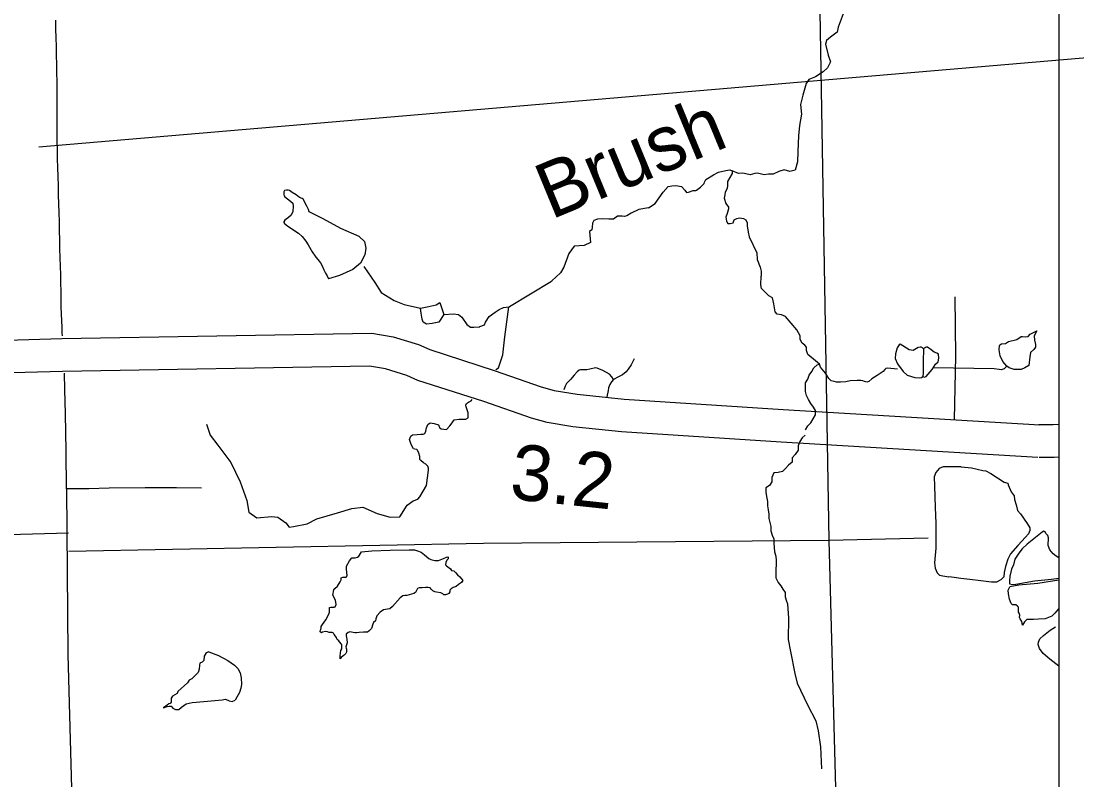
# Model space of a CAD drawing. Extents: x 1367863 to 1368197, y 380048 to 380261.
# Drawn here: x 1368072.73 to 1368103.87, y 380118.75 to 380141.12 of the extents above; entities that cross this region are included whole.
import ezdxf

# ---------------------------------------------------------------- set-up
doc = ezdxf.new("R2010")
doc.units = 0
for name, color, linetype in [('Level 10', 7, 'Continuous'), ('Level 31', 7, 'Continuous'), ('Level 32', 7, 'Continuous'), ('Level 35', 7, 'Continuous'), ('Level 48', 7, 'Continuous'), ('Level 5', 7, 'Continuous'), ('R_Draft', 7, 'Continuous'), ('R_No Plot', 7, 'Continuous')]:
    doc.layers.add(name, color=color, linetype=linetype)

msp = doc.modelspace()

# ---------------------------------------------------------------- linework, layer by layer
at = {"layer": 'Level 10'}
for points in [[(1368071.322, 380131.689), (1368073.931, 380131.759), (1368083.074, 380131.916), (1368083.701, 380131.811), (1368084.454, 380131.587), (1368084.786, 380131.435), (1368086.684, 380130.822), (1368088.074, 380130.341), (1368088.457, 380130.233), (1368089.133, 380130.121), (1368090.52, 380129.974), (1368095.213, 380129.671), (1368102.782, 380129.222)], [(1368102.724, 380128.253), (1368095.153, 380128.702), (1368090.438, 380129.008), (1368089.002, 380129.159), (1368088.244, 380129.285), (1368087.783, 380129.415), (1368086.377, 380129.902), (1368084.433, 380130.529), (1368084.112, 380130.677), (1368083.482, 380130.864), (1368083.002, 380130.944), (1368073.953, 380130.789), (1368071.363, 380130.72)], [(1368102.747, 380129.223), (1368103.169, 380129.227), (1368103.344, 380129.239)], [(1368103.344, 380128.267), (1368103.206, 380128.258), (1368102.759, 380128.252)]]:
    msp.add_lwpolyline(points, dxfattribs=at)
at = {"layer": 'Level 31'}
for points in [[(1368073.947, 380131.842), (1368073.945, 380131.925), (1368073.941, 380132.1), (1368073.93, 380132.288), (1368073.923, 380132.489), (1368073.914, 380132.699), (1368073.915, 380132.927), (1368073.91, 380133.158), (1368073.904, 380133.397), (1368073.898, 380133.644), (1368073.891, 380133.895), (1368073.885, 380134.151), (1368073.876, 380134.411), (1368073.87, 380134.674), (1368073.864, 380134.938), (1368073.865, 380135.211), (1368073.851, 380135.473), (1368073.842, 380135.738), (1368073.835, 380136.004), (1368073.828, 380136.27), (1368073.82, 380136.537), (1368073.814, 380136.802), (1368073.808, 380137.065), (1368073.8, 380137.326), (1368073.797, 380137.585), (1368073.795, 380137.837), (1368073.797, 380138.091), (1368073.797, 380138.34), (1368073.793, 380138.591), (1368073.796, 380138.84), (1368073.794, 380139.093), (1368073.79, 380139.345), (1368073.787, 380139.598), (1368073.782, 380139.853), (1368073.776, 380140.111), (1368073.77, 380140.372), (1368073.764, 380140.633), (1368073.758, 380140.894), (1368073.753, 380141.154)], [(1368074.069, 380127.329), (1368074.054, 380128.437), (1368074.041, 380129.554), (1368074.02, 380130.246), (1368074.008, 380130.745)], [(1368078.05, 380127.349), (1368077.312, 380127.356), (1368076.391, 380127.356), (1368075.327, 380127.349), (1368074.731, 380127.329), (1368074.318, 380127.329), (1368074.069, 380127.329)], [(1368074.069, 380127.329), (1368074.105, 380122.448), (1368074.225, 380118.134)], [(1368103.344, 380122.103), (1368103.078, 380122.303), (1368102.88, 380122.476), (1368102.774, 380122.622), (1368102.734, 380122.741), (1368102.738, 380122.812), (1368102.782, 380122.904), (1368102.888, 380123.002), (1368103.083, 380123.161), (1368103.246, 380123.258)]]:
    msp.add_lwpolyline(points, dxfattribs=at)
at = {"layer": 'Level 32'}
for points in [[(1368100.259, 380129.371), (1368100.304, 380131.239), (1368100.281, 380132.997)], [(1368090.815, 380131.165), (1368090.728, 380130.982), (1368090.64, 380130.863), (1368090.577, 380130.784), (1368090.465, 380130.696), (1368090.354, 380130.632), (1368090.203, 380130.553), (1368090.147, 380130.489), (1368090.1, 380130.41), (1368090.06, 380130.306), (1368090.044, 380130.227), (1368090.01, 380130.046)], [(1368090.203, 380130.553), (1368090.155, 380130.632), (1368090.084, 380130.712), (1368089.893, 380130.823), (1368089.726, 380130.887), (1368089.67, 380130.895), (1368089.503, 380130.855), (1368089.416, 380130.839), (1368089.32, 380130.839), (1368089.233, 380130.839), (1368089.193, 380130.831), (1368089.129, 380130.784), (1368089.042, 380130.68), (1368088.939, 380130.553), (1368088.819, 380130.434), (1368088.78, 380130.362), (1368088.735, 380130.254)]]:
    msp.add_lwpolyline(points, dxfattribs=at)
at = {"layer": 'Level 35'}
for points in [[(1368097.066, 380141.572), (1368096.831, 380140.945), (1368096.802, 380140.799), (1368096.606, 380140.652), (1368096.489, 380140.554), (1368096.459, 380140.446), (1368096.538, 380140.123), (1368096.606, 380139.918), (1368096.518, 380139.741), (1368096.391, 380139.624), (1368096.166, 380139.477), (1368095.97, 380139.399), (1368095.882, 380139.281), (1368095.784, 380138.939), (1368095.715, 380138.665), (1368095.745, 380138.381), (1368095.686, 380138.048), (1368095.657, 380137.744), (1368095.637, 380137.275), (1368095.627, 380136.971), (1368095.567, 380136.728), (1368095.404, 380136.69), (1368095.24, 380136.74), (1368095.077, 380136.69), (1368094.914, 380136.614), (1368094.775, 380136.614), (1368094.65, 380136.589), (1368094.448, 380136.64), (1368094.373, 380136.627), (1368094.235, 380136.589), (1368094.021, 380136.64), (1368093.895, 380136.627), (1368093.7, 380136.712)], [(1368091.239, 380135.617), (1368091.433, 380135.749), (1368091.666, 380136.083), (1368091.821, 380136.246), (1368091.922, 380136.269), (1368092.038, 380136.277), (1368092.209, 380136.246), (1368092.31, 380136.137), (1368092.357, 380136.067), (1368092.419, 380136.083), (1368092.551, 380136.129), (1368092.636, 380136.129), (1368092.652, 380136.137), (1368092.768, 380136.23), (1368092.877, 380136.331), (1368092.892, 380136.37), (1368092.931, 380136.455), (1368093.149, 380136.587), (1368093.296, 380136.673), (1368093.513, 380136.719), (1368093.638, 380136.735), (1368093.7, 380136.712), (1368093.7, 380136.626), (1368093.568, 380136.393), (1368093.568, 380136.277), (1368093.56, 380136.191), (1368093.498, 380136.083), (1368093.49, 380135.997), (1368093.467, 380135.904), (1368093.521, 380135.749), (1368093.591, 380135.64), (1368093.591, 380135.586), (1368093.552, 380135.446), (1368093.521, 380135.337), (1368093.537, 380135.228), (1368093.575, 380135.159), (1368093.645, 380135.151), (1368093.731, 380135.174), (1368093.762, 380135.259), (1368093.839, 380135.306), (1368093.925, 380135.322), (1368094.041, 380135.298), (1368094.111, 380135.259), (1368094.142, 380135.174), (1368094.15, 380135.089), (1368094.173, 380134.902), (1368094.204, 380134.762), (1368094.429, 380134.293), (1368094.445, 380134.092), (1368094.53, 380133.866), (1368094.561, 380133.75), (1368094.561, 380133.602)], [(1368082.856, 380134.627), (1368082.7, 380134.774), (1368082.164, 380135.012), (1368081.637, 380135.294), (1368081.264, 380135.478), (1368081.223, 380135.503), (1368081.207, 380135.572), (1368081.158, 380135.667), (1368081.052, 380135.871), (1368081.023, 380135.896), (1368080.945, 380135.924), (1368080.847, 380135.998), (1368080.724, 380136.068), (1368080.647, 380136.129), (1368080.61, 380136.137), (1368080.561, 380136.133), (1368080.503, 380136.125), (1368080.483, 380136.092), (1368080.483, 380136.027), (1368080.483, 380136.014), (1368080.491, 380135.973), (1368080.508, 380135.937), (1368080.63, 380135.851), (1368080.745, 380135.752), (1368080.753, 380135.662), (1368080.745, 380135.507), (1368080.7, 380135.405), (1368080.618, 380135.327), (1368080.553, 380135.282), (1368080.512, 380135.249), (1368080.479, 380135.204), (1368080.475, 380135.184), (1368080.503, 380135.155), (1368080.602, 380135.081), (1368080.908, 380134.873), (1368081.023, 380134.774), (1368081.133, 380134.631), (1368081.195, 380134.521), (1368081.313, 380134.32), (1368081.424, 380134.164), (1368081.485, 380134.091), (1368081.563, 380133.997), (1368081.608, 380133.907), (1368081.657, 380133.784), (1368081.706, 380133.686), (1368081.755, 380133.612), (1368081.8, 380133.526)], [(1368091.239, 380135.617), (1368090.952, 380135.57), (1368090.727, 380135.461), (1368090.595, 380135.384), (1368090.532, 380135.36), (1368090.455, 380135.368), (1368090.323, 380135.368), (1368090.206, 380135.283), (1368090.067, 380135.283), (1368089.88, 380135.29), (1368089.733, 380135.283), (1368089.624, 380135.244), (1368089.585, 380135.166), (1368089.578, 380135.05), (1368089.562, 380134.972), (1368089.5, 380134.918), (1368089.529, 380134.593), (1368089.337, 380134.508), (1368089.04, 380134.487), (1368088.891, 380134.274), (1368088.742, 380133.87), (1368088.636, 380133.7), (1368088.381, 380133.466), (1368088.373, 380133.447), (1368087.14, 380132.699)], [(1368082.856, 380134.627), (1368082.897, 380134.426), (1368082.864, 380134.234), (1368082.737, 380133.984), (1368082.512, 380133.796), (1368082.119, 380133.62), (1368081.8, 380133.526)], [(1368082.843, 380133.882), (1368083.162, 380133.414), (1368083.353, 380133.116), (1368083.736, 380132.882), (1368084.026, 380132.769), (1368084.506, 380132.656)], [(1368098.577, 380130.863), (1368098.29, 380130.889), (1368098.239, 380130.882), (1368098.204, 380130.849), (1368098.161, 380130.788), (1368097.983, 380130.674), (1368097.821, 380130.575), (1368097.74, 380130.494), (1368097.679, 380130.474), (1368097.603, 380130.496), (1368097.555, 380130.517), (1368097.497, 380130.529), (1368097.395, 380130.527), (1368097.187, 380130.517), (1368097.058, 380130.489), (1368096.898, 380130.479), (1368096.782, 380130.479), (1368096.716, 380130.494), (1368096.629, 380130.517), (1368096.551, 380130.588), (1368096.457, 380130.742), (1368096.305, 380130.917), (1368096.28, 380131.011), (1368096.163, 380131.102), (1368095.933, 380131.288), (1368095.901, 380131.407), (1368095.901, 380131.511), (1368095.846, 380131.566), (1368095.766, 380131.622), (1368095.711, 380131.733), (1368095.711, 380131.844), (1368095.608, 380132.019), (1368095.274, 380132.416), (1368095.155, 380132.464), (1368095.036, 380132.479), (1368094.972, 380132.551), (1368094.932, 380132.789), (1368094.893, 380132.964), (1368094.782, 380133.019), (1368094.567, 380133.242), (1368094.551, 380133.345), (1368094.561, 380133.602)], [(1368084.506, 380132.656), (1368084.703, 380132.698), (1368084.971, 380132.755), (1368085.084, 380132.825), (1368085.197, 380132.472), (1368085.056, 380132.247), (1368084.859, 380132.204), (1368084.689, 380132.19), (1368084.591, 380132.247), (1368084.562, 380132.331), (1368084.534, 380132.515), (1368084.506, 380132.656)], [(1368085.197, 380132.472), (1368085.487, 380132.489), (1368085.634, 380132.474), (1368085.727, 380132.388), (1368085.875, 380132.179), (1368085.983, 380132.101), (1368086.084, 380132.101), (1368086.263, 380132.109), (1368086.263, 380132.117), (1368086.403, 380132.171), (1368086.426, 380132.241), (1368086.535, 380132.412), (1368086.713, 380132.544), (1368086.83, 380132.614), (1368086.962, 380132.676), (1368087.117, 380132.699), (1368087.14, 380132.699)], [(1368086.736, 380130.847), (1368086.807, 380130.894), (1368086.935, 380131.277), (1368086.998, 380131.808), (1368087.117, 380132.699)], [(1368101.598, 380131.578), (1368101.649, 380131.604), (1368101.768, 380131.617), (1368101.854, 380131.671), (1368102.104, 380131.735), (1368102.229, 380131.822), (1368102.271, 380131.825), (1368102.357, 380131.815), (1368102.431, 380131.825), (1368102.492, 380131.889), (1368102.549, 380131.918), (1368102.693, 380131.985)], [(1368102.693, 380131.985), (1368102.613, 380131.844), (1368102.62, 380131.719), (1368102.652, 380131.588), (1368102.652, 380131.511), (1368102.604, 380131.437), (1368102.508, 380131.354), (1368102.482, 380131.219), (1368102.453, 380130.97)], [(1368099.195, 380131.497), (1368099.043, 380131.405), (1368098.924, 380131.426), (1368098.66, 380131.596), (1368098.627, 380131.58), (1368098.574, 380131.484), (1368098.521, 380131.312), (1368098.508, 380131.172), (1368098.576, 380131.017), (1368098.746, 380130.792), (1368098.863, 380130.68), (1368099.091, 380130.614), (1368099.22, 380130.601), (1368099.291, 380130.617), (1368099.327, 380130.639), (1368099.378, 380130.622), (1368099.431, 380130.645), (1368099.606, 380130.847), (1368099.702, 380131.005), (1368099.781, 380131.073), (1368099.796, 380131.185), (1368099.786, 380131.304), (1368099.74, 380131.327), (1368099.667, 380131.357), (1368099.573, 380131.426), (1368099.469, 380131.504), (1368099.433, 380131.507), (1368099.403, 380131.494), (1368099.35, 380131.456), (1368099.314, 380131.492), (1368099.279, 380131.512), (1368099.253, 380131.512), (1368099.203, 380131.499)], [(1368099.35, 380131.456), (1368099.335, 380131.088), (1368099.34, 380130.749), (1368099.327, 380130.639)], [(1368102.453, 380130.97), (1368102.338, 380130.899), (1368102.226, 380130.854), (1368102.027, 380130.845), (1368101.87, 380130.902), (1368101.803, 380130.947), (1368101.688, 380131.082), (1368101.611, 380131.251), (1368101.579, 380131.428), (1368101.585, 380131.556), (1368101.598, 380131.578)], [(1368095.868, 380129.065), (1368095.937, 380129.184), (1368096.022, 380129.278), (1368096.09, 380129.397), (1368096.158, 380129.508), (1368096.158, 380129.636), (1368096.099, 380129.738), (1368096.022, 380129.849), (1368095.954, 380129.96), (1368095.894, 380130.079), (1368095.868, 380130.199), (1368095.868, 380130.327), (1368095.868, 380130.455), (1368095.937, 380130.565), (1368095.979, 380130.685), (1368096.056, 380130.787), (1368096.116, 380130.898), (1368096.21, 380130.983), (1368096.28, 380131.011)], [(1368101.803, 380130.947), (1368101.723, 380130.867), (1368101.64, 380130.841), (1368101.582, 380130.854), (1368101.435, 380130.873), (1368099.636, 380130.896)], [(1368078.195, 380129.235), (1368078.302, 380128.917), (1368078.535, 380128.619), (1368078.918, 380128.109), (1368079.195, 380127.535), (1368079.386, 380126.982), (1368079.45, 380126.642), (1368079.684, 380126.472), (1368080.13, 380126.514), (1368080.3, 380126.493), (1368080.534, 380126.323), (1368080.641, 380126.195), (1368080.768, 380126.216), (1368081.172, 380126.301), (1368081.449, 380126.45), (1368082.065, 380126.62), (1368082.49, 380126.748), (1368082.809, 380126.79), (1368083.235, 380126.599), (1368083.617, 380126.493), (1368083.903, 380126.503), (1368084.121, 380126.844), (1368084.291, 380126.976), (1368084.431, 380127.023), (1368084.493, 380127.093), (1368084.687, 380127.427), (1368084.742, 380127.877), (1368084.742, 380127.939), (1368084.726, 380128.002), (1368084.672, 380128.056), (1368084.602, 380128.095), (1368084.524, 380128.165), (1368084.493, 380128.196), (1368084.493, 380128.281), (1368084.462, 380128.382), (1368084.423, 380128.467), (1368084.4, 380128.491), (1368084.346, 380128.499), (1368084.307, 380128.514), (1368084.237, 380128.638), (1368084.183, 380128.786), (1368084.221, 380128.887), (1368084.276, 380128.926), (1368084.416, 380128.933), (1368084.516, 380128.941), (1368084.594, 380128.941), (1368084.641, 380128.957), (1368084.672, 380129.027), (1368084.687, 380129.128), (1368084.726, 380129.229), (1368084.796, 380129.275), (1368084.912, 380129.26), (1368085.037, 380129.213), (1368085.075, 380129.135), (1368085.122, 380129.104), (1368085.277, 380129.081), (1368085.378, 380129.19), (1368085.44, 380129.275), (1368085.502, 380129.361), (1368085.65, 380129.384), (1368085.751, 380129.384), (1368085.852, 380129.384), (1368085.914, 380129.423), (1368085.921, 380129.477), (1368085.921, 380129.57), (1368085.859, 380129.749), (1368085.852, 380129.795), (1368085.867, 380129.85), (1368085.929, 380129.881), (1368086.007, 380129.927), (1368086.038, 380129.962)], [(1368095.86, 380128.911), (1368095.766, 380128.834), (1368095.698, 380128.724), (1368095.655, 380128.596), (1368095.647, 380128.468), (1368095.561, 380128.34), (1368095.476, 380128.246), (1368095.476, 380128.118), (1368095.365, 380128.024), (1368095.28, 380127.931), (1368095.186, 380127.845), (1368095.058, 380127.811), (1368094.93, 380127.803), (1368094.871, 380127.666), (1368094.871, 380127.538), (1368094.802, 380127.427), (1368094.7, 380127.359), (1368094.7, 380127.231), (1368094.717, 380127.103), (1368094.743, 380126.958), (1368094.743, 380126.831), (1368094.768, 380126.711), (1368094.785, 380126.583), (1368094.785, 380126.455)], [(1368100.463, 380127.98), (1368099.931, 380127.98), (1368099.808, 380127.926), (1368099.715, 380127.813), (1368099.66, 380127.68), (1368099.67, 380127.409), (1368099.69, 380126.793), (1368099.715, 380126.305), (1368099.715, 380125.576), (1368099.675, 380125.143), (1368099.695, 380124.99), (1368099.749, 380124.848), (1368099.818, 380124.788), (1368099.916, 380124.764), (1368100.099, 380124.734)], [(1368100.463, 380127.98), (1368100.767, 380127.951), (1368101.097, 380127.872), (1368101.191, 380127.862), (1368101.333, 380127.783), (1368101.727, 380127.527), (1368101.831, 380127.497), (1368101.845, 380127.448), (1368101.929, 380127.241), (1368102.023, 380127.128), (1368102.033, 380127.02), (1368102.077, 380126.862), (1368102.116, 380126.695), (1368102.205, 380126.591), (1368102.407, 380126.305), (1368102.486, 380126.182), (1368102.486, 380126.099), (1368102.441, 380126.005), (1368102.353, 380125.907), (1368102.126, 380125.66), (1368101.919, 380125.409), (1368101.836, 380125.251), (1368101.762, 380125.035), (1368101.732, 380124.867), (1368101.713, 380124.739), (1368101.629, 380124.646), (1368101.506, 380124.577), (1368101.353, 380124.577), (1368101.043, 380124.621), (1368100.718, 380124.66), (1368100.447, 380124.69), (1368100.25, 380124.715), (1368100.099, 380124.734)], [(1368094.785, 380126.455), (1368094.819, 380126.341), (1368094.845, 380126.222), (1368094.845, 380126.094), (1368094.879, 380125.966), (1368094.93, 380125.855), (1368094.93, 380125.727), (1368094.939, 380125.599), (1368094.956, 380125.471), (1368094.99, 380125.343), (1368094.999, 380125.215), (1368094.999, 380125.088), (1368094.99, 380124.96), (1368094.99, 380124.832), (1368094.99, 380124.704), (1368095.058, 380124.567), (1368095.144, 380124.474), (1368095.203, 380124.371), (1368095.263, 380124.269), (1368095.271, 380124.141), (1368095.306, 380124.013), (1368095.336, 380123.939)], [(1368103.344, 380125.291), (1368103.342, 380125.292), (1368103.259, 380125.341), (1368103.175, 380125.415), (1368103.071, 380125.533), (1368103.027, 380125.661), (1368103.032, 380125.888), (1368103.012, 380125.952), (1368102.958, 380126.016), (1368102.938, 380126.065), (1368102.899, 380126.08), (1368102.845, 380126.056), (1368102.747, 380125.97)], [(1368102.747, 380125.97), (1368102.403, 380125.7), (1368102.26, 380125.562), (1368102.162, 380125.434), (1368102.043, 380125.251), (1368101.999, 380125.089), (1368101.945, 380124.961), (1368101.891, 380124.759), (1368101.886, 380124.621), (1368101.881, 380124.532)], [(1368081.949, 380123.071), (1368081.928, 380123.086), (1368081.903, 380123.091), (1368081.858, 380123.091), (1368081.813, 380123.091), (1368081.767, 380123.116), (1368081.712, 380123.121), (1368081.616, 380123.101), (1368081.591, 380123.086), (1368081.556, 380123.116), (1368081.551, 380123.141), (1368081.571, 380123.182), (1368081.576, 380123.227), (1368081.576, 380123.267), (1368081.616, 380123.328), (1368081.722, 380123.469), (1368081.808, 380123.635), (1368081.823, 380123.69), (1368081.823, 380123.736), (1368081.828, 380123.826), (1368081.868, 380123.836), (1368081.964, 380123.836), (1368081.994, 380123.851), (1368082.019, 380123.922), (1368081.999, 380124.048), (1368081.923, 380124.194), (1368081.954, 380124.355), (1368081.979, 380124.395), (1368082.059, 380124.456), (1368082.14, 380124.592), (1368082.175, 380124.647), (1368082.175, 380124.708), (1368082.215, 380124.728), (1368082.321, 380124.728), (1368082.346, 380124.768), (1368082.331, 380124.969), (1368082.326, 380125.045), (1368082.412, 380125.206), (1368082.482, 380125.292), (1368082.588, 380125.297), (1368082.648, 380125.317), (1368082.689, 380125.342), (1368082.709, 380125.377), (1368082.769, 380125.468)], [(1368082.769, 380125.468), (1368083.071, 380125.498), (1368083.62, 380125.524), (1368084.174, 380125.529), (1368084.335, 380125.529), (1368084.42, 380125.503), (1368084.531, 380125.463), (1368084.632, 380125.382)], [(1368084.632, 380125.382), (1368084.753, 380125.272), (1368084.813, 380125.247), (1368084.929, 380125.221), (1368085.04, 380125.221), (1368085.191, 380125.272), (1368085.281, 380125.317), (1368085.317, 380125.327), (1368085.327, 380125.317), (1368085.322, 380125.267), (1368085.291, 380125.231), (1368085.261, 380125.156), (1368085.251, 380125.09), (1368085.276, 380125.055), (1368085.397, 380124.969), (1368085.422, 380124.924), (1368085.498, 380124.909), (1368085.543, 380124.864), (1368085.599, 380124.798), (1368085.669, 380124.733), (1368085.755, 380124.622), (1368085.719, 380124.572), (1368085.634, 380124.506), (1368085.558, 380124.446), (1368085.473, 380124.421), (1368085.417, 380124.38), (1368085.377, 380124.34), (1368085.372, 380124.29), (1368085.347, 380124.244), (1368085.312, 380124.219), (1368085.246, 380124.204), (1368085.201, 380124.204), (1368085.171, 380124.234), (1368085.11, 380124.259), (1368084.984, 380124.285), (1368084.929, 380124.29), (1368084.879, 380124.325), (1368084.823, 380124.37), (1368084.793, 380124.415), (1368084.738, 380124.421), (1368084.657, 380124.421), (1368084.556, 380124.415), (1368084.501, 380124.415), (1368084.471, 380124.41), (1368084.426, 380124.39), (1368084.385, 380124.31), (1368084.365, 380124.274), (1368084.31, 380124.239), (1368084.108, 380124.184), (1368084.048, 380124.184), (1368083.988, 380124.179), (1368083.907, 380124.113), (1368083.68, 380123.856), (1368083.605, 380123.791), (1368083.534, 380123.781), (1368083.419, 380123.761), (1368083.318, 380123.695), (1368083.222, 380123.584), (1368083.197, 380123.494), (1368083.182, 380123.433), (1368083.122, 380123.388), (1368083.101, 380123.338), (1368083.066, 380123.212), (1368083.001, 380123.146), (1368082.95, 380123.106), (1368082.905, 380123.106), (1368082.825, 380123.106), (1368082.704, 380123.091), (1368082.618, 380123.081), (1368082.573, 380123.081), (1368082.427, 380123.111), (1368082.407, 380123.106), (1368082.376, 380123.096), (1368082.321, 380123.046), (1368082.321, 380122.995), (1368082.341, 380122.9), (1368082.346, 380122.784), (1368082.311, 380122.673), (1368082.321, 380122.628), (1368082.326, 380122.597), (1368082.326, 380122.552), (1368082.326, 380122.517), (1368082.306, 380122.471), (1368082.256, 380122.426), (1368082.225, 380122.401), (1368082.175, 380122.356), (1368082.14, 380122.315), (1368082.14, 380122.401), (1368082.15, 380122.482), (1368082.16, 380122.567), (1368082.195, 380122.612), (1368082.195, 380122.673), (1368082.195, 380122.723), (1368082.185, 380122.748), (1368082.125, 380122.814), (1368082.1, 380122.844), (1368082.049, 380122.884), (1368082.039, 380122.91), (1368082.029, 380122.945), (1368081.969, 380123.03), (1368081.949, 380123.071)], [(1368101.881, 380124.532), (1368101.973, 380124.509), (1368102.072, 380124.519), (1368102.618, 380124.612), (1368103.121, 380124.662), (1368103.344, 380124.698)], [(1368103.344, 380124.636), (1368102.722, 380124.543), (1368102.161, 380124.489), (1368101.895, 380124.435)], [(1368103.344, 380123.8), (1368103.224, 380123.667), (1368103.131, 380123.578), (1368102.934, 380123.494), (1368102.742, 380123.484), (1368102.589, 380123.48), (1368102.397, 380123.475), (1368102.328, 380123.411), (1368102.264, 380123.307), (1368102.249, 380123.42), (1368102.2, 380123.499), (1368102.18, 380123.539), (1368102.185, 380123.608), (1368102.17, 380123.662), (1368102.146, 380123.691), (1368102.146, 380123.75), (1368102.146, 380123.814), (1368102.146, 380123.839), (1368102.121, 380123.869), (1368102.067, 380123.908), (1368102.033, 380123.908), (1368101.969, 380123.908), (1368101.929, 380123.952), (1368101.88, 380124.076), (1368101.86, 380124.238), (1368101.85, 380124.346), (1368101.895, 380124.435)], [(1368095.336, 380123.939), (1368095.37, 380123.516), (1368095.357, 380122.89), (1368095.421, 380122.533), (1368095.548, 380121.882), (1368095.625, 380121.602), (1368095.931, 380120.964), (1368096.174, 380120.491), (1368096.238, 380120.198), (1368096.314, 380119.726), (1368096.339, 380119.07)], [(1368078.268, 380122.522), (1368078.188, 380122.492), (1368078.127, 380122.396), (1368078.117, 380122.265), (1368078.067, 380122.22), (1368078.001, 380122.184), (1368077.991, 380122.129), (1368077.986, 380122.008), (1368077.956, 380121.917), (1368077.765, 380121.726), (1368077.684, 380121.686), (1368077.634, 380121.605), (1368077.352, 380121.353), (1368077.332, 380121.293), (1368077.196, 380121.217), (1368077.156, 380121.157), (1368077.156, 380121.086), (1368077.156, 380121.036), (1368077.13, 380121.001), (1368077.09, 380120.991), (1368077.04, 380120.955), (1368076.995, 380120.92), (1368076.929, 380120.875), (1368077.04, 380120.915), (1368077.1, 380120.925), (1368077.156, 380120.92), (1368077.201, 380120.86), (1368077.287, 380120.825), (1368077.382, 380120.825), (1368077.463, 380120.89), (1368077.594, 380120.986), (1368077.775, 380121.026), (1368078.122, 380121.056), (1368078.656, 380121.112), (1368078.762, 380121.132), (1368078.867, 380121.076), (1368078.958, 380121.061), (1368079.044, 380121.096)], [(1368078.268, 380122.522), (1368078.55, 380122.411), (1368078.832, 380122.265), (1368079.028, 380122.129), (1368079.124, 380122.028), (1368079.195, 380121.902), (1368079.22, 380121.756), (1368079.23, 380121.555), (1368079.21, 380121.454), (1368079.169, 380121.323), (1368079.094, 380121.182), (1368079.044, 380121.096)]]:
    msp.add_lwpolyline(points, dxfattribs=at)
at = {"layer": 'Level 5'}
for points in [[(1368096.197, 380146.617), (1368096.554, 380125.803)], [(1368057.075, 380125.565), (1368074.125, 380126.034)], [(1368096.554, 380125.803), (1368086.368, 380125.713), (1368074.137, 380125.485)], [(1368099.487, 380125.878), (1368096.554, 380125.803)], [(1368096.554, 380125.803), (1368096.94, 380111.58)]]:
    msp.add_lwpolyline(points, dxfattribs=at)
at = {"layer": 'R_Draft'}
msp.add_lwpolyline([(1368073.255, 380137.414), (1368112.592, 380140.769)], dxfattribs=at)
at = {"layer": 'R_No Plot'}
msp.add_lwpolyline([(1367959.444, 380177.46), (1368103.344, 380177.46), (1368103.344, 380096.865), (1367959.444, 380096.865)], close=True, dxfattribs=at)

# ---------------------------------------------------------------- texts
at = {"layer": 'Level 35'}
msp.add_text('Brush', height=1.6394, rotation=22.4581, dxfattribs=at).set_placement((1368088.358, 380135.261))
at = {"layer": 'Level 48'}
msp.add_text('3.2', height=1.6394, rotation=353.9889, dxfattribs=at).set_placement((1368087.11, 380127.04))

doc.saveas('drawing.dxf')
